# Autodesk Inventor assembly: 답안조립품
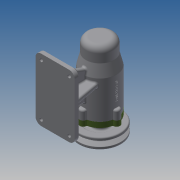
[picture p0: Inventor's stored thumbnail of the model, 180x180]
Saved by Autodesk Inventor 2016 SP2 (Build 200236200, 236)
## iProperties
Created: 2019-07
Part Number: 답안조립품
Document SubType Name: Assembly
Designer: EZ
Author: EZ
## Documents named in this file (12)
- X:\490704V1037 정현호\답안조립품.iam
- X:\490704V1037 정현호\본체.ipt
- X:\490704V1037 정현호\490704V1037\V벨트풀리.ipt
- X:\490704V1037 정현호\490704V1037\멈춤나사 M3.ipt
- X:\490704V1037 정현호\490704V1037\베어링 6004.ipt
- X:\490704V1037 정현호\490704V1037\베어링 51202.ipt
- X:\490704V1037 정현호\490704V1037\볼트 M4.ipt
- X:\490704V1037 정현호\490704V1037\어댑터슬리브.ipt
- X:\490704V1037 정현호\490704V1037\오일 실.ipt
- X:\490704V1037 정현호\490704V1037\축.ipt
- X:\490704V1037 정현호\490704V1037\커버.ipt
- X:\490704V1037 정현호\490704V1037\키 5 x 5 x 16.ipt
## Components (1 placed, 1 different names)
1. V벨트풀리:1
